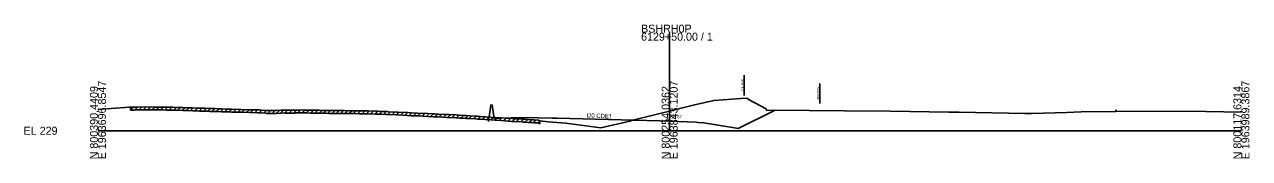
# Model space of a CAD drawing. Extents: x -26 to 1986619, y -10 to 827846.
# Drawn here: x -25.7 to 402.8, y 9490.3 to 9537.1 of the extents above; entities that cross this region are included whole.
import ezdxf

# ---------------------------------------------------------------- set-up
doc = ezdxf.new("R2010")
doc.units = 0
for name, color, linetype in [('Default', 7, 'Continuous'), ('RD_EX_Road', 7, 'Continuous'), ('RD_PD_ALT2_TrvlWay', 7, 'Continuous'), ('RD_PD_ALT5_LnLine', 7, 'Continuous'), ('RD_PD_ALT5_TrvlWay', 7, 'Continuous'), ('RD_PD_PaveDit', 7, 'Continuous'), ('RD_Sketch2', 7, 'Continuous'), ('RD_XS_ExRW', 7, 'Continuous'), ('RD_XS_NewRW', 7, 'Continuous')]:
    doc.layers.add(name, color=color, linetype=linetype)

msp = doc.modelspace()

# ---------------------------------------------------------------- linework, layer by layer
at = {"layer": 'RD_EX_Road'}
for p, q in [((200, 9500), (200, 9534.26)), ((0, 9500), (200, 9500)), ((200, 9500), (400, 9500))]:
    msp.add_line(p, q, dxfattribs=at)
at = {"layer": 'RD_PD_ALT5_LnLine'}
msp.add_lwpolyline([(0, 9507.42), (6.12, 9507.85), (11.04, 9508.22), (11.43, 9508.24), (12.61, 9508.24), (12.96, 9508.28), (13.39, 9508.29), (16.49, 9508.32), (19.39, 9508.28), (20.03, 9508.27), (21.31, 9508.27), (22.79, 9508.25), (23.81, 9508.23), (26.19, 9508.18), (27.47, 9508.14), (29.64, 9508.07), (31.11, 9508.03), (33.09, 9507.96), (34.72, 9507.91), (35.58, 9507.89), (36.54, 9507.86), (37.48, 9507.83), (38.46, 9507.8), (39.17, 9507.77), (39.79, 9507.75), (40.93, 9507.71), (42.13, 9507.67), (43.26, 9507.63), (44.49, 9507.59), (45.8, 9507.56), (46.72, 9507.53), (49.46, 9507.47), (50.14, 9507.45), (53.1, 9507.34), (53.58, 9507.33), (55.98, 9507.26), (56.5, 9507.25), (57.21, 9507.21), (58.9, 9507.11), (59.12, 9507.07), (60.45, 9507.02), (62.32, 9507.03), (64.12, 9507.14), (65.14, 9507.2), (65.5, 9507.18), (67.47, 9507.13), (68.04, 9507.13), (68.6, 9507.13), (68.93, 9507.21), (69.32, 9507.21), (70.77, 9507.24), (71.24, 9507.25), (72.12, 9507.23), (72.81, 9507.21), (74.23, 9507.18), (74.67, 9507.17), (75.12, 9507.17), (77.37, 9507.13), (78.04, 9507.12), (78.71, 9507.11), (79.83, 9507.09), (80.77, 9507.07), (82.41, 9507.04), (84.29, 9507.02), (86.09, 9507.02), (87.85, 9507), (88.7, 9507), (89.8, 9506.98), (91.24, 9506.96), (93.42, 9506.93), (94.46, 9506.9), (97.1, 9506.82), (97.46, 9506.8), (97.87, 9506.79), (99.33, 9506.74), (100.78, 9506.68), (101.23, 9506.66), (101.64, 9506.65), (104.46, 9506.53), (104.95, 9506.5), (108.24, 9506.32), (109.53, 9506.26), (111.75, 9506.16), (115.4, 9505.99), (117.44, 9505.89), (117.83, 9505.87), (118.73, 9505.83), (119.06, 9505.81), (122, 9505.68), (122.73, 9505.64), (125.28, 9505.5), (125.8, 9505.47), (126.44, 9505.43), (127.74, 9505.35), (128.72, 9505.3), (130.11, 9505.22), (132.02, 9505.1), (132.76, 9505.06), (133.78, 9504.99), (135.57, 9504.88), (137.44, 9504.76), (138.99, 9504.65), (141.04, 9504.52), (142.44, 9504.42), (143.54, 9504.34), (144.74, 9504.28), (145.88, 9504.21), (148.3, 9504.07), (148.81, 9504.04), (149.28, 9504.01), (150.62, 9503.92), (152.08, 9503.83), (152.56, 9503.8), (154.03, 9503.73), (154.62, 9503.46), (157.48, 9503.14), (163.66, 9502.59), (175.91, 9500.99), (186.07, 9503.35), (187.64, 9503.75), (200, 9506.87), (203.07, 9507.64), (208.24, 9508.89), (215.47, 9510.6), (224.87, 9511.27), (226.96, 9511.42), (227.83, 9510.82), (233.76, 9507.61), (233.86, 9507.16), (248.84, 9507.08), (261.13, 9506.94), (277.16, 9506.78), (297.71, 9506.54), (301.23, 9506.5), (324.3, 9506.05), (326.7, 9506), (338.95, 9506.39), (343.96, 9506.55), (356, 9506.74), (356.1, 9507.19), (356.18, 9506.78), (387.57, 9506.71), (400, 9506.43)], dxfattribs=at)
at = {"layer": 'RD_PD_PaveDit'}
for p, q in [((11.39, 9507.24), (12.39, 9508.24)), ((11.39, 9507.24), (11.39, 9508.24)), ((11.39, 9507.24), (11.43, 9507.24)), ((11.43, 9507.24), (12.61, 9507.24)), ((12.61, 9507.24), (12.96, 9507.28)), ((12.89, 9507.27), (13.91, 9508.3)), ((12.96, 9507.28), (13.39, 9507.29)), ((13.39, 9507.29), (16.49, 9507.32)), ((14.39, 9507.3), (15.4, 9508.31)), ((15.89, 9507.31), (16.89, 9508.31)), ((16.49, 9507.32), (19.39, 9507.28)), ((17.39, 9507.31), (18.38, 9508.29)), ((18.89, 9507.29), (19.88, 9508.27)), ((19.39, 9507.28), (20.03, 9507.27)), ((20.03, 9507.27), (21.31, 9507.27)), ((20.39, 9507.27), (21.39, 9508.27)), ((21.31, 9507.27), (22.79, 9507.25)), ((21.89, 9507.26), (22.88, 9508.25)), ((22.79, 9507.25), (23.81, 9507.23)), ((23.39, 9507.24), (24.37, 9508.22)), ((23.81, 9507.23), (26.19, 9507.18)), ((24.89, 9507.21), (25.87, 9508.19)), ((26.19, 9507.18), (27.47, 9507.14)), ((26.39, 9507.18), (27.36, 9508.15)), ((27.47, 9507.14), (29.64, 9507.07)), ((27.89, 9507.13), (28.86, 9508.1)), ((29.39, 9507.08), (30.36, 9508.05)), ((29.64, 9507.07), (31.11, 9507.03)), ((30.89, 9507.03), (31.86, 9508)), ((31.11, 9507.03), (33.09, 9506.96)), ((32.39, 9506.98), (33.36, 9507.95)), ((33.09, 9506.96), (34.72, 9506.91)), ((33.89, 9506.94), (34.86, 9507.91)), ((34.72, 9506.91), (35.58, 9506.89)), ((35.39, 9506.89), (36.36, 9507.86)), ((35.58, 9506.89), (36.54, 9506.86)), ((36.54, 9506.86), (37.48, 9506.83)), ((36.89, 9506.85), (37.86, 9507.81)), ((37.48, 9506.83), (38.46, 9506.8)), ((38.39, 9506.8), (39.36, 9507.77)), ((38.46, 9506.8), (39.17, 9506.77)), ((39.17, 9506.77), (39.79, 9506.75)), ((39.79, 9506.75), (40.93, 9506.71)), ((39.89, 9506.75), (40.86, 9507.72)), ((40.93, 9506.71), (42.13, 9506.67)), ((41.39, 9506.7), (42.36, 9507.66)), ((42.13, 9506.67), (43.26, 9506.63)), ((42.89, 9506.64), (43.86, 9507.61)), ((43.26, 9506.63), (44.49, 9506.59)), ((44.39, 9506.59), (45.36, 9507.57)), ((44.49, 9506.59), (45.8, 9506.56)), ((45.8, 9506.56), (46.72, 9506.53)), ((45.89, 9506.55), (46.87, 9507.53)), ((46.72, 9506.53), (49.46, 9506.47)), ((47.39, 9506.52), (48.37, 9507.49)), ((48.89, 9506.48), (49.86, 9507.45)), ((49.46, 9506.47), (50.14, 9506.45)), ((50.14, 9506.45), (53.1, 9506.34)), ((50.39, 9506.44), (51.36, 9507.4)), ((51.89, 9506.39), (52.86, 9507.35)), ((53.1, 9506.34), (53.58, 9506.33)), ((53.39, 9506.34), (54.36, 9507.31)), ((53.58, 9506.33), (55.98, 9506.26)), ((54.89, 9506.29), (55.86, 9507.27)), ((55.98, 9506.26), (56.5, 9506.25)), ((56.39, 9506.25), (57.34, 9507.2)), ((56.5, 9506.25), (57.21, 9506.21)), ((57.21, 9506.21), (58.9, 9506.11)), ((57.89, 9506.17), (58.83, 9507.11)), ((58.9, 9506.11), (59.12, 9506.07)), ((59.12, 9506.07), (60.45, 9506.02)), ((59.39, 9506.06), (60.36, 9507.02)), ((60.45, 9506.02), (62.32, 9506.03)), ((60.89, 9506.02), (61.9, 9507.03)), ((62.32, 9506.03), (64.12, 9506.14)), ((62.39, 9506.04), (63.46, 9507.1)), ((63.89, 9506.13), (64.95, 9507.19)), ((64.12, 9506.14), (65.14, 9506.2)), ((65.14, 9506.2), (65.5, 9506.18)), ((65.39, 9506.19), (66.36, 9507.16)), ((65.5, 9506.18), (67.47, 9506.13)), ((66.89, 9506.14), (67.88, 9507.13)), ((67.47, 9506.13), (68.04, 9506.13)), ((68.04, 9506.13), (68.6, 9506.13)), ((68.39, 9506.13), (69.47, 9507.22)), ((68.6, 9506.13), (68.93, 9506.21)), ((68.93, 9506.21), (69.32, 9506.21)), ((69.32, 9506.21), (70.77, 9506.24)), ((69.89, 9506.22), (70.91, 9507.24)), ((70.77, 9506.24), (71.24, 9506.25)), ((71.24, 9506.25), (72.12, 9506.23)), ((71.39, 9506.24), (72.37, 9507.22)), ((72.12, 9506.23), (72.81, 9506.21)), ((72.81, 9506.21), (74.23, 9506.18)), ((72.89, 9506.21), (73.87, 9507.19)), ((74.23, 9506.18), (74.67, 9506.17)), ((74.39, 9506.18), (75.37, 9507.16)), ((74.67, 9506.17), (75.12, 9506.17)), ((75.12, 9506.17), (77.37, 9506.13)), ((75.89, 9506.16), (76.87, 9507.14)), ((77.37, 9506.13), (78.04, 9506.12)), ((77.39, 9506.13), (78.37, 9507.11)), ((78.04, 9506.12), (78.71, 9506.11)), ((78.71, 9506.11), (79.83, 9506.09)), ((78.89, 9506.1), (79.87, 9507.09)), ((79.83, 9506.09), (80.77, 9506.07)), ((80.39, 9506.08), (81.37, 9507.06)), ((80.77, 9506.07), (82.41, 9506.04)), ((81.89, 9506.05), (82.88, 9507.04)), ((82.41, 9506.04), (84.29, 9506.02)), ((83.39, 9506.03), (84.38, 9507.02)), ((84.29, 9506.02), (86.09, 9506.02)), ((84.89, 9506.02), (85.89, 9507.02)), ((86.09, 9506.02), (87.85, 9506)), ((86.39, 9506.01), (87.38, 9507.01)), ((87.85, 9506), (88.7, 9506)), ((87.89, 9506), (88.88, 9506.99)), ((88.7, 9506), (89.8, 9505.98)), ((89.39, 9505.99), (90.38, 9506.97)), ((89.8, 9505.98), (91.24, 9505.96)), ((90.89, 9505.97), (91.88, 9506.95)), ((91.24, 9505.96), (93.42, 9505.93)), ((92.39, 9505.94), (93.37, 9506.93)), ((93.42, 9505.93), (94.46, 9505.9)), ((93.89, 9505.91), (94.86, 9506.89)), ((94.46, 9505.9), (97.1, 9505.82)), ((95.39, 9505.87), (96.36, 9506.84)), ((96.89, 9505.82), (97.86, 9506.79)), ((97.1, 9505.82), (97.46, 9505.8)), ((97.46, 9505.8), (97.87, 9505.79)), ((97.87, 9505.79), (99.33, 9505.74)), ((98.39, 9505.77), (99.36, 9506.74)), ((99.33, 9505.74), (100.78, 9505.68)), ((99.89, 9505.72), (100.85, 9506.68)), ((100.78, 9505.68), (101.23, 9505.66)), ((101.23, 9505.66), (101.64, 9505.65)), ((101.39, 9505.66), (102.35, 9506.62)), ((101.64, 9505.65), (104.46, 9505.53)), ((102.89, 9505.59), (103.85, 9506.55)), ((104.39, 9505.53), (105.34, 9506.48)), ((104.46, 9505.53), (104.95, 9505.5)), ((104.95, 9505.5), (108.24, 9505.32)), ((105.89, 9505.45), (106.84, 9506.4)), ((107.39, 9505.37), (108.34, 9506.32)), ((108.24, 9505.32), (109.53, 9505.26)), ((108.89, 9505.29), (109.85, 9506.25)), ((109.53, 9505.26), (111.75, 9505.16)), ((110.39, 9505.23), (111.35, 9506.18)), ((111.75, 9505.16), (115.4, 9504.99)), ((111.89, 9505.16), (112.85, 9506.11)), ((113.39, 9505.09), (114.35, 9506.04)), ((114.89, 9505.02), (115.84, 9505.97)), ((115.4, 9504.99), (117.44, 9504.89)), ((116.39, 9504.94), (117.34, 9505.9)), ((117.44, 9504.89), (117.83, 9504.87)), ((117.83, 9504.87), (118.73, 9504.83)), ((117.89, 9504.87), (118.84, 9505.82)), ((119.39, 9504.8), (120.35, 9505.75)), ((120.89, 9504.73), (121.85, 9505.68)), ((122.39, 9504.66), (123.34, 9505.61)), ((123.89, 9504.58), (124.84, 9505.52)), ((125.39, 9504.49), (126.33, 9505.44)), ((126.89, 9504.4), (127.83, 9505.35)), ((128.39, 9504.32), (129.34, 9505.26)), ((129.89, 9504.23), (130.83, 9505.17)), ((131.39, 9504.14), (132.33, 9505.08)), ((132.89, 9504.05), (133.83, 9504.99)), ((134.39, 9503.95), (135.33, 9504.89)), ((118.73, 9504.83), (119.06, 9504.81)), ((119.06, 9504.81), (122, 9504.68)), ((122, 9504.68), (122.73, 9504.64)), ((122.73, 9504.64), (125.28, 9504.5)), ((125.28, 9504.5), (125.8, 9504.47)), ((125.8, 9504.47), (126.44, 9504.43)), ((126.44, 9504.43), (127.74, 9504.35)), ((127.74, 9504.35), (128.72, 9504.3)), ((128.72, 9504.3), (130.11, 9504.22)), ((130.11, 9504.22), (132.02, 9504.1)), ((132.02, 9504.1), (132.76, 9504.06)), ((132.76, 9504.06), (133.78, 9503.99)), ((133.78, 9503.99), (135.57, 9503.88)), ((135.57, 9503.88), (137.44, 9503.76)), ((135.89, 9503.86), (136.83, 9504.8)), ((137.39, 9503.76), (138.33, 9504.7)), ((137.44, 9503.76), (138.99, 9503.65)), ((138.89, 9503.66), (139.83, 9504.6)), ((138.99, 9503.65), (141.04, 9503.52)), ((140.39, 9503.56), (141.33, 9504.5)), ((141.04, 9503.52), (142.44, 9503.42)), ((141.89, 9503.46), (142.82, 9504.4)), ((142.44, 9503.42), (143.54, 9503.34)), ((143.39, 9503.35), (144.34, 9504.3)), ((143.54, 9503.34), (144.74, 9503.28)), ((144.74, 9503.28), (145.88, 9503.21)), ((144.89, 9503.27), (145.84, 9504.22)), ((145.88, 9503.21), (148.3, 9503.07)), ((146.39, 9503.18), (147.33, 9504.13)), ((147.89, 9503.09), (148.83, 9504.04)), ((148.3, 9503.07), (148.81, 9503.04)), ((148.81, 9503.04), (149.28, 9503.01)), ((149.28, 9503.01), (150.62, 9502.92)), ((149.39, 9503), (150.33, 9503.94)), ((150.62, 9502.92), (152.08, 9502.83)), ((150.89, 9502.91), (151.83, 9503.85)), ((152.08, 9502.83), (152.56, 9502.8)), ((152.39, 9502.82), (153.34, 9503.77)), ((152.56, 9502.8), (154.03, 9502.73)), ((153.89, 9502.74), (154.62, 9503.46)), ((154.03, 9502.73), (154.62, 9502.46)), ((154.62, 9503.46), (154.62, 9502.46))]:
    msp.add_line(p, q, dxfattribs=at)
at = {"layer": 'RD_Sketch2'}
msp.add_lwpolyline([(136.66, 9503.28), (137.41, 9508.95), (137.91, 9508.95), (138.66, 9504.27), (140.39, 9504.34), (148.67, 9504.67), (158.93, 9504.39), (160.67, 9504.36), (196.42, 9503.4), (200, 9503.32), (200, 9503.32), (200, 9503.32), (209.28, 9502.94), (209.99, 9502.91), (211.99, 9502.75), (223.39, 9500.84), (223.99, 9500.74), (236.44, 9506.96), (236.84, 9507.16)], dxfattribs=at)
at = {"layer": 'RD_XS_ExRW'}
msp.add_line((226.07, 9512.36), (226.07, 9519.36), dxfattribs=at)
at = {"layer": 'RD_XS_NewRW'}
msp.add_line((252.58, 9509.49), (252.58, 9516.49), dxfattribs=at)

# ---------------------------------------------------------------- texts
at = {"layer": 'Default'}
msp.add_text('-', height=0.0001, dxfattribs=at).set_placement((0, 9500))
at = {"layer": 'RD_EX_Road'}
for s, p in [('BSHRH0P', (190, 9534.26)), ('6129+50.00 / 1', (190, 9531.46)), ('EL 229', (-26, 9498.6))]:
    msp.add_text(s, height=2.8, dxfattribs=at).set_placement(p)
for s, p in [('N 800390.4409', (0, 9490)), ('E 1963696.8547', (2.8, 9490)), ('N 800254.0362', (200, 9490)), ('E 1963843.1207', (202.8, 9490)), ('N 800117.6314', (400, 9490)), ('E 1963989.3867', (402.8, 9490))]:
    msp.add_text(s, height=2.8, rotation=90, dxfattribs=at).set_placement(p)
at = {"layer": 'RD_PD_ALT2_TrvlWay'}
msp.add_text('I20 CDE1', height=1.5, rotation=358.0852, dxfattribs=at).set_placement((170.87, 9504.61))
at = {"layer": 'RD_PD_ALT5_TrvlWay'}
msp.add_text('235.87', height=1, dxfattribs=at).set_placement((200, 9504.37))
at = {"layer": 'RD_XS_ExRW'}
msp.add_text('EX. R/W ', height=0.75, rotation=90, dxfattribs=at).set_placement((225.81, 9514.03))
at = {"layer": 'RD_XS_NewRW'}
msp.add_text('NEW R/W ', height=0.75, rotation=90, dxfattribs=at).set_placement((252.33, 9510.62))

doc.saveas('drawing.dxf')
